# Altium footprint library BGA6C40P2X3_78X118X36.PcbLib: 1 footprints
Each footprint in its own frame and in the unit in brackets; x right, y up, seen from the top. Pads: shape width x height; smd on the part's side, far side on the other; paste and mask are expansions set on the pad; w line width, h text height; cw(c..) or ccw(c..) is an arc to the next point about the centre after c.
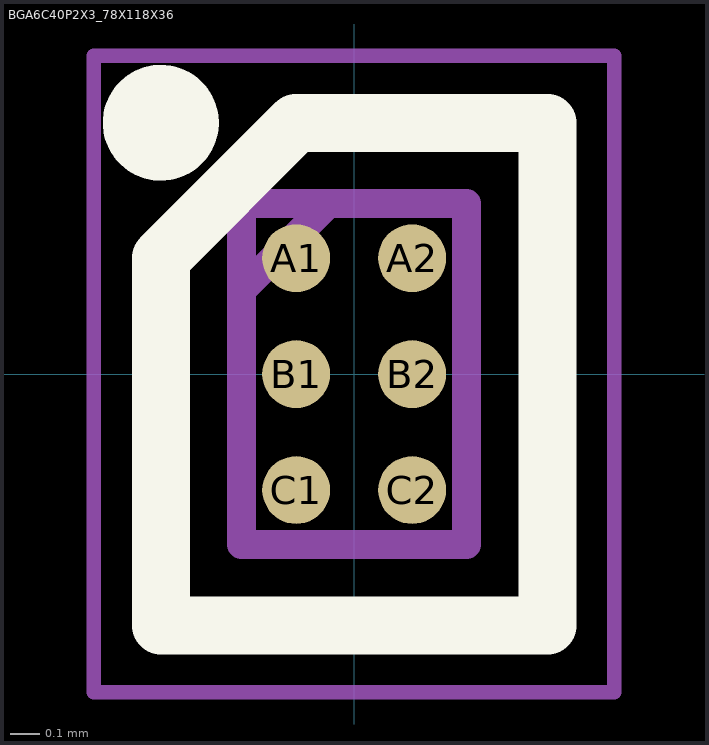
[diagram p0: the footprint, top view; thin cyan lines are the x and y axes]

## BGA6C40P2X3_78X118X36 [mm]
pads (6):
  round 0.234 smd: A1(-0.2,0.4) A2(0.2,0.4) B1(-0.2,0) B2(0.2,0) C1(-0.2,-0.4) C2(0.2,-0.4)
Top Overlay:
  circle w0.2: c-0.667,0.867 r0.1
  lines w0.2: -0.667,-0.867 0.667,-0.867 0.667,0.867 -0.2,0.867 -0.667,0.4 -0.667,-0.867
Mechanical 15:
  lines w0.1: -0.388,0.289 -0.089,0.588 ; -0.388,-0.587 0.387,-0.587 0.387,0.588 -0.388,0.588 -0.388,-0.587
Mechanical 20:
  lines w0.05: -0.898,-1.097 0.897,-1.097 0.897,1.098 -0.898,1.098 -0.898,-1.097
